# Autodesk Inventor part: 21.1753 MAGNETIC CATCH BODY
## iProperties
Created: 2007-03
Part Number: 21.1753 MAGNETIC CATCH BODY
Document SubType Name: Modeling
Designer: Andy Moles
Material: ABS Plastic
Mass: 7.81929 g
Surface Area: 29.1544 cm^2
Volume: 7.37669 cm^3
Density: 1.06 g/cm^3
Author: Andy Moles
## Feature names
1. Extrusion1
2. Extrusion2
3. Extrusion3
4. Extrusion4
5. Fillet1
6. Fillet2
